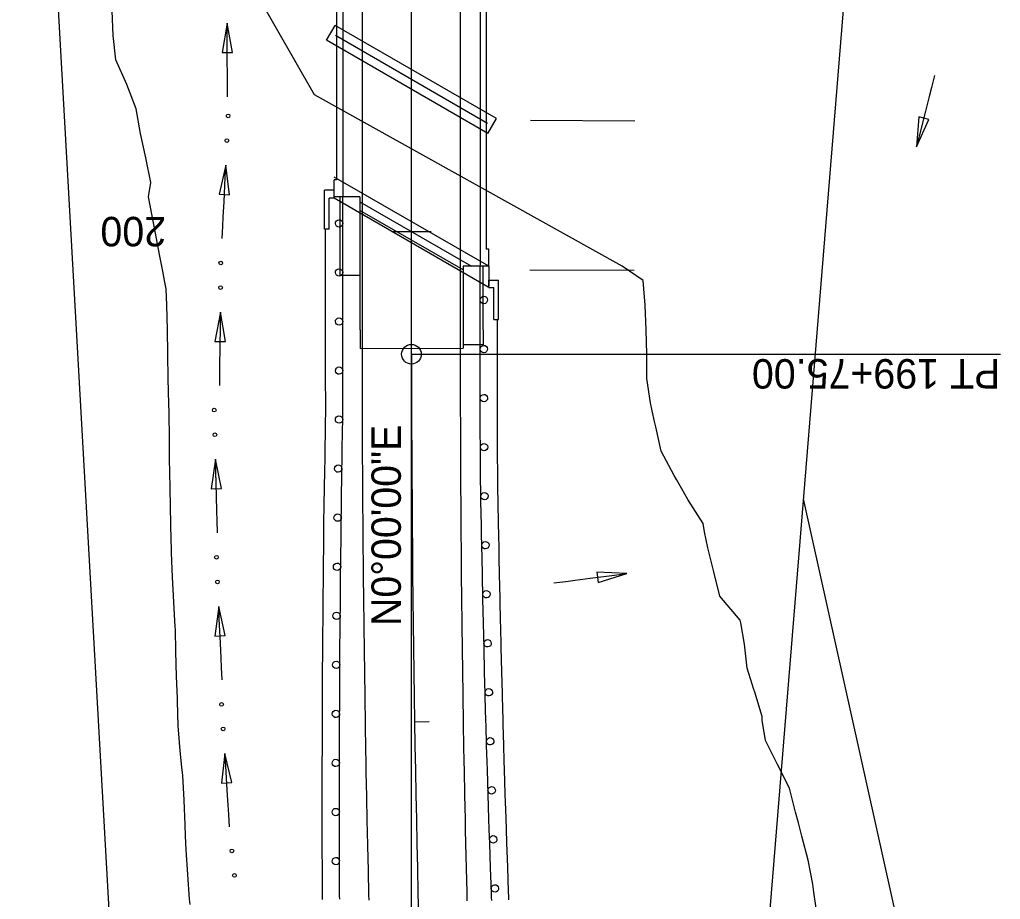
# Model space of a CAD drawing. Extents: x 1 to 1477871, y 1 to 1872901.
# Drawn here: x 1438531.3 to 1438731.2, y 1869800.2 to 1869979.6 of the extents above; entities that cross this region are included whole.
import ezdxf

# ---------------------------------------------------------------- set-up
doc = ezdxf.new("R2010")
doc.units = 0
for name, color, linetype in [('B_Centerline', 7, 'Continuous'), ('B_Concrete', 7, 'Continuous'), ('B_Concrete hidden', 7, 'Continuous'), ('R_Concrete Hidden', 7, 'Continuous'), ('R_Horz Alg', 7, 'Continuous'), ('R_Horz Alg Annot', 7, 'Continuous'), ('R_No Plot', 7, 'Continuous'), ('R_Proposed Const Limits_Cut', 7, 'Continuous'), ('R_Proposed Road_Lane', 7, 'Continuous'), ('R_Proposed Road_Shoulder', 7, 'Continuous'), ('R_ROW', 7, 'Continuous'), ('R_Steel', 7, 'Continuous'), ('R_Temp Easement', 7, 'Continuous'), ('R_Water', 7, 'Continuous')]:
    doc.layers.add(name, color=color, linetype=linetype)

msp = doc.modelspace()

# ---------------------------------------------------------------- linework, layer by layer
at = {"layer": 'B_Centerline'}
msp.add_line((1438626.69, 1869958.4), (1438595.69, 1869976.3), dxfattribs=at)
at = {"layer": 'B_Concrete'}
for p, q in [((1438597.19, 1870067.43), (1438597.19, 1869943.43)), ((1438595.94, 1870063.93), (1438595.94, 1869946.93)), ((1438625.19, 1870053.28), (1438625.19, 1869929.28)), ((1438626.44, 1870049.78), (1438626.44, 1869932.78)), ((1438595.44, 1869943.43), (1438595.44, 1869946.93)), ((1438595.94, 1869946.93), (1438595.44, 1869946.93)), ((1438593.44, 1869936.81), (1438593.44, 1869944.81)), ((1438595.44, 1869944.81), (1438593.44, 1869944.81)), ((1438595.44, 1869943.14), (1438595.44, 1869944.81)), ((1438594.44, 1869936.81), (1438594.44, 1869943.14)), ((1438595.44, 1869943.14), (1438594.44, 1869943.14)), ((1438600.69, 1869943.43), (1438595.44, 1869943.43)), ((1438596.61, 1869943.43), (1438596.61, 1869927.43)), ((1438600.69, 1869943.43), (1438600.69, 1869916.35)), ((1438600.69, 1869942.41), (1438623.44, 1869929.28)), ((1438621.69, 1869928.56), (1438600.69, 1869940.68)), ((1438594.44, 1869936.81), (1438593.44, 1869936.81)), ((1438626.94, 1869932.78), (1438626.44, 1869932.78)), ((1438626.94, 1869929.28), (1438626.94, 1869932.78)), ((1438626.94, 1869929.28), (1438621.69, 1869929.28)), ((1438621.69, 1869929.28), (1438621.69, 1869928.56)), ((1438621.69, 1869928.56), (1438621.69, 1869916.35)), ((1438626.94, 1869929.28), (1438626.94, 1869925.24)), ((1438596.61, 1869927.43), (1438600.69, 1869927.43)), ((1438626.94, 1869926.45), (1438628.94, 1869926.45)), ((1438626.94, 1869924.95), (1438626.94, 1869926.45)), ((1438628.94, 1869918.45), (1438628.94, 1869926.45)), ((1438626.94, 1869924.95), (1438627.94, 1869924.95)), ((1438627.94, 1869918.45), (1438627.94, 1869924.95)), ((1438627.94, 1869918.45), (1438628.94, 1869918.45)), ((1438600.7, 1869912.53), (1438621.7, 1869912.56)), ((1438625.78, 1869913.28), (1438621.7, 1869913.28))]:
    msp.add_line(p, q, dxfattribs=at)
msp.add_lwpolyline([(1438625.78, 1869916.35), (1438625.78, 1869916.35), (1438625.78, 1869929.28)], dxfattribs=at)
for radius, end in [(3284.54, 180.06661), (3263.55, 180.06661), (3259.46, 180.05393)]:
    msp.add_arc((1441885.24, 1869916.35), radius, 180, end, dxfattribs=at)
at = {"layer": 'B_Concrete hidden'}
for p, q in [((1438628.51, 1869959.37), (1438595.61, 1869978.37)), ((1438626.94, 1869929.28), (1438595.44, 1869947.47)), ((1438626.82, 1869925.02), (1438595.44, 1869943.14))]:
    msp.add_line(p, q, dxfattribs=at)
at = {"layer": 'R_Concrete Hidden'}
for p, q in [((1438593.86, 1869975.34), (1438595.61, 1869978.37)), ((1438626.76, 1869956.34), (1438593.86, 1869975.34)), ((1438626.76, 1869956.34), (1438628.51, 1869959.37))]:
    msp.add_line(p, q, dxfattribs=at)
at = {"layer": 'R_Horz Alg'}
msp.add_line((1438611.19, 1869911.35), (1438611.19, 1870085.35), dxfattribs=at)
msp.add_arc((1443194.86, 1869911.35), 4583.66, 180, 183.99213, dxfattribs=at)
at = {"layer": 'R_Horz Alg Annot'}
msp.add_line((1438611.19, 1869751.6), (1438611.19, 1869911.35), dxfattribs=at)
for points in [[(1438607.19, 1869936.35), (1438615.19, 1869936.35)], [(1438611.19, 1869911.35), (1438731.19, 1869911.35)], [(1438614.81, 1869836.41), (1438611.81, 1869836.36)]]:
    msp.add_lwpolyline(points, dxfattribs=at)
msp.add_circle((1438611.19, 1869911.35), 2, dxfattribs=at)
at = {"layer": 'R_No Plot'}
for p, q in [((1438635.47, 1869959.05), (1438656.69, 1869958.95)), ((1438635.32, 1869928.55), (1438656.54, 1869928.45))]:
    msp.add_line(p, q, dxfattribs=at)
at = {"layer": 'R_Proposed Const Limits_Cut'}
for points in [[(1438654.11, 1869929.27), (1438591.42, 1869964.25), (1438576.24, 1869990.87), (1438572, 1869991.35)], [(1438566.07, 1869799.15), (1438565.97, 1869800.25), (1438565.6, 1869805.29), (1438565.29, 1869810.33), (1438565.16, 1869813.16), (1438565.07, 1869815.38), (1438564.89, 1869820.43), (1438564.57, 1869825.48), (1438564.37, 1869827.18), (1438564.05, 1869830.52), (1438563.72, 1869834.74), (1438563.68, 1869835.57), (1438563.5, 1869840.62), (1438563.48, 1869841.2), (1438563.32, 1869845.67), (1438563.2, 1869850.72), (1438563.07, 1869855.22), (1438563.04, 1869855.77), (1438562.77, 1869860.82), (1438562.51, 1869865.87), (1438562.36, 1869869.25), (1438562.3, 1869870.93), (1438562.2, 1869874.28), (1438562.16, 1869875.98), (1438562.08, 1869881.03), (1438562.04, 1869883.28), (1438561.99, 1869885.26), (1438561.98, 1869886.08), (1438561.87, 1869891.14), (1438561.85, 1869896.19), (1438561.83, 1869897.32), (1438561.8, 1869899.55), (1438561.76, 1869901.25), (1438561.64, 1869906.3), (1438561.54, 1869911.35), (1438561.45, 1869916.35), (1438561.36, 1869921.35), (1438561.17, 1869924.67), (1438560.85, 1869926.35), (1438560.49, 1869928.27), (1438560.3, 1869929.28), (1438559.91, 1869931.35), (1438558.96, 1869936.35), (1438558.01, 1869941.35), (1438557.63, 1869943.42), (1438558.11, 1869946.35), (1438557.08, 1869951.35), (1438556, 1869956.35), (1438555.09, 1869961.35), (1438553.19, 1869966.35), (1438550.94, 1869971.35), (1438550.37, 1869976.35), (1438550.17, 1869981.35)], [(1438693.68, 1869798.4), (1438693.21, 1869801.65), (1438693.13, 1869802.23), (1438692.98, 1869803.29), (1438692.04, 1869808.19), (1438690.75, 1869813.07), (1438690.03, 1869815.81), (1438689.46, 1869817.96), (1438688.19, 1869822.85), (1438685.8, 1869827.73), (1438684.97, 1869829.37), (1438683.33, 1869832.6), (1438682.65, 1869836.71), (1438682.62, 1869837.52), (1438681.16, 1869842.42), (1438680.98, 1869842.98), (1438679.58, 1869847.32), (1438679.05, 1869852.24), (1438678.28, 1869856.62), (1438678.15, 1869857.15), (1438674.05, 1869862.04), (1438672.79, 1869866.96), (1438671.99, 1869870.25), (1438671.6, 1869871.88), (1438670.9, 1869875.15), (1438670.6, 1869876.81), (1438667.52, 1869881.72), (1438666.27, 1869883.92), (1438665.17, 1869885.84), (1438664.71, 1869886.64), (1438662.06, 1869891.57), (1438660.98, 1869896.52), (1438660.74, 1869897.62), (1438660.26, 1869899.8), (1438659.9, 1869901.46), (1438659.15, 1869906.41), (1438659.16, 1869911.35), (1438659.04, 1869916.35), (1438658.8, 1869921.35), (1438658.53, 1869924.67), (1438658.41, 1869926.35), (1438654.11, 1869929.27)]]:
    msp.add_lwpolyline(points, dxfattribs=at)
at = {"layer": 'R_Proposed Road_Lane'}
for points in [[(1438602.54, 1869800.04), (1438602.52, 1869801.12), (1438602.4, 1869806.13), (1438602.29, 1869811.14), (1438602.23, 1869813.95), (1438602.18, 1869816.15), (1438602.08, 1869821.16), (1438601.98, 1869826.17), (1438601.95, 1869827.86), (1438601.89, 1869831.18), (1438601.82, 1869835.37), (1438601.81, 1869836.19), (1438601.73, 1869841.2), (1438601.72, 1869841.78), (1438601.66, 1869846.21), (1438601.59, 1869851.22), (1438601.53, 1869855.69), (1438601.52, 1869856.23), (1438601.47, 1869861.25), (1438601.42, 1869866.26), (1438601.38, 1869869.6), (1438601.37, 1869871.27), (1438601.34, 1869874.59), (1438601.33, 1869876.28), (1438601.29, 1869881.29), (1438601.28, 1869883.52), (1438601.27, 1869885.48), (1438601.26, 1869886.3), (1438601.24, 1869891.31), (1438601.22, 1869896.32), (1438601.22, 1869897.44), (1438601.21, 1869899.65), (1438601.21, 1869901.33), (1438601.2, 1869906.34), (1438601.19, 1869911.35), (1438601.19, 1869916.35), (1438601.19, 1869921.35), (1438601.19, 1869924.67), (1438601.19, 1869926.35), (1438601.19, 1869928.27), (1438601.19, 1869929.28), (1438601.19, 1869931.35), (1438601.19, 1869936.35), (1438601.19, 1869941.35), (1438601.19, 1869943.42), (1438601.19, 1869946.35), (1438601.19, 1869951.35), (1438601.19, 1869956.35), (1438601.19, 1869961.35), (1438601.19, 1869966.35), (1438601.19, 1869971.35), (1438601.19, 1869976.35), (1438601.19, 1869981.35)], [(1438622.55, 1869799.93), (1438622.54, 1869800.52), (1438622.51, 1869801.6), (1438622.39, 1869806.59), (1438622.28, 1869811.58), (1438622.22, 1869814.37), (1438622.18, 1869816.57), (1438622.07, 1869821.55), (1438621.98, 1869826.54), (1438621.95, 1869828.23), (1438621.89, 1869831.53), (1438621.82, 1869835.7), (1438621.81, 1869836.52), (1438621.73, 1869841.51), (1438621.72, 1869842.08), (1438621.65, 1869846.5), (1438621.59, 1869851.49), (1438621.53, 1869855.93), (1438621.52, 1869856.47), (1438621.47, 1869861.46), (1438621.41, 1869866.45), (1438621.38, 1869869.79), (1438621.37, 1869871.44), (1438621.34, 1869874.75), (1438621.33, 1869876.43), (1438621.29, 1869881.42), (1438621.28, 1869883.64), (1438621.27, 1869885.59), (1438621.26, 1869886.41), (1438621.24, 1869891.4), (1438621.22, 1869896.39), (1438621.22, 1869897.5), (1438621.21, 1869899.7), (1438621.21, 1869901.38), (1438621.2, 1869906.36), (1438621.19, 1869911.35), (1438621.19, 1869916.35), (1438621.19, 1869921.35), (1438621.19, 1869924.67), (1438621.19, 1869926.35), (1438621.19, 1869928.27), (1438621.19, 1869929.28), (1438621.19, 1869931.35), (1438621.19, 1869936.35), (1438621.19, 1869941.35), (1438621.19, 1869943.42), (1438621.19, 1869946.35), (1438621.19, 1869951.35), (1438621.19, 1869956.35), (1438621.19, 1869961.35), (1438621.19, 1869966.35), (1438621.19, 1869971.35), (1438621.19, 1869976.35), (1438621.19, 1869981.35)]]:
    msp.add_lwpolyline(points, dxfattribs=at)
at = {"layer": 'R_Proposed Road_Shoulder'}
for points in [[(1438593.06, 1869800.21), (1438593.05, 1869800.9), (1438593.03, 1869805.92), (1438593.02, 1869810.94), (1438593.02, 1869813.75), (1438593.02, 1869815.96), (1438593.02, 1869820.98), (1438593.02, 1869826.01), (1438593.02, 1869827.7), (1438593.03, 1869831.03), (1438593.04, 1869835.23), (1438593.04, 1869836.05), (1438593.06, 1869841.07), (1438593.07, 1869841.65), (1438593.09, 1869846.09), (1438593.12, 1869851.11), (1438593.15, 1869855.59), (1438593.16, 1869856.13), (1438593.2, 1869861.15), (1438593.25, 1869866.18), (1438593.28, 1869869.53), (1438593.3, 1869871.2), (1438593.34, 1869874.53), (1438593.36, 1869876.22), (1438593.43, 1869881.24), (1438593.46, 1869883.47), (1438593.48, 1869885.43), (1438593.5, 1869886.26), (1438593.57, 1869891.28), (1438593.65, 1869896.29), (1438593.67, 1869897.41), (1438593.71, 1869899.63), (1438593.71, 1869901.31), (1438593.7, 1869906.33), (1438593.69, 1869911.35), (1438593.69, 1869916.35), (1438593.69, 1869921.35), (1438593.69, 1869924.67), (1438593.69, 1869926.35), (1438593.69, 1869928.27), (1438593.69, 1869929.28), (1438593.69, 1869931.35), (1438593.69, 1869936.35), (1438593.69, 1869936.81)], [(1438631.03, 1869800.13), (1438631.01, 1869800.73), (1438630.97, 1869801.81), (1438630.8, 1869806.78), (1438630.63, 1869811.76), (1438630.54, 1869814.55), (1438630.47, 1869816.74), (1438630.31, 1869821.72), (1438630.16, 1869826.7), (1438630.1, 1869828.37), (1438630.01, 1869831.67), (1438629.89, 1869835.83), (1438629.87, 1869836.65), (1438629.73, 1869841.63), (1438629.72, 1869842.2), (1438629.6, 1869846.61), (1438629.48, 1869851.59), (1438629.37, 1869856.03), (1438629.36, 1869856.57), (1438629.24, 1869861.55), (1438629.13, 1869866.53), (1438629.06, 1869869.86), (1438629.03, 1869871.51), (1438628.96, 1869874.81), (1438628.93, 1869876.49), (1438628.84, 1869881.47), (1438628.8, 1869883.69), (1438628.77, 1869885.63), (1438628.76, 1869886.45), (1438628.74, 1869891.43), (1438628.72, 1869896.41), (1438628.72, 1869897.52), (1438628.71, 1869899.72), (1438628.71, 1869901.39), (1438628.7, 1869906.37), (1438628.69, 1869911.35), (1438628.69, 1869916.35), (1438628.69, 1869918.45)]]:
    msp.add_lwpolyline(points, dxfattribs=at)
at = {"layer": 'R_ROW'}
for p, q in [((1438587.34, 1869127.27), (1438531.34, 1870121.98)), ((1438701.19, 1870006.35), (1438676.17, 1869699.24))]:
    msp.add_line(p, q, dxfattribs=at)
at = {"layer": 'R_Steel'}
for points in [[(1438596.56, 1869800.22), (1438596.55, 1869800.91), (1438596.53, 1869805.93), (1438596.52, 1869810.95), (1438596.52, 1869813.76), (1438596.52, 1869815.96), (1438596.52, 1869820.98), (1438596.52, 1869826), (1438596.52, 1869827.69), (1438596.53, 1869831.02), (1438596.54, 1869835.22), (1438596.54, 1869836.04), (1438596.56, 1869841.05), (1438596.57, 1869841.63), (1438596.59, 1869846.07), (1438596.62, 1869851.09), (1438596.65, 1869855.56), (1438596.66, 1869856.1), (1438596.7, 1869861.12), (1438596.75, 1869866.14), (1438596.78, 1869869.49), (1438596.84, 1869874.49), (1438596.86, 1869876.17), (1438596.93, 1869881.19), (1438596.96, 1869883.43), (1438596.98, 1869885.38), (1438597, 1869886.2), (1438597.07, 1869891.22), (1438597.15, 1869896.24), (1438597.17, 1869897.35), (1438597.21, 1869899.6), (1438597.2, 1869901.32), (1438597.2, 1869906.34), (1438597.19, 1869911.35), (1438597.19, 1869943.43)], [(1438627.53, 1869800.01), (1438627.51, 1869800.6), (1438627.47, 1869801.68), (1438627.3, 1869806.66), (1438627.13, 1869811.64), (1438627.04, 1869814.43), (1438626.97, 1869816.63), (1438626.81, 1869821.61), (1438626.66, 1869826.59), (1438626.61, 1869828.27), (1438626.51, 1869831.57), (1438626.39, 1869835.74), (1438626.37, 1869836.55), (1438626.23, 1869841.54), (1438626.22, 1869842.11), (1438626.1, 1869846.52), (1438625.98, 1869851.5), (1438625.86, 1869856.49), (1438625.74, 1869861.47), (1438625.63, 1869866.45), (1438625.56, 1869869.79), (1438625.46, 1869874.75), (1438625.43, 1869876.42), (1438625.34, 1869881.4), (1438625.3, 1869883.63), (1438625.27, 1869885.59), (1438625.26, 1869886.43), (1438625.24, 1869891.41), (1438625.22, 1869896.4), (1438625.21, 1869899.71), (1438625.21, 1869901.38), (1438625.2, 1869906.37), (1438625.19, 1869911.35), (1438625.19, 1869929.28)]]:
    msp.add_lwpolyline(points, dxfattribs=at)
for centre, major_axis in [((1438596.44, 1869938.01), (-0.512, -0.548)), ((1438596.44, 1869928.01), (-0.512, -0.548)), ((1438625.94, 1869922.4), (-0.512, -0.548)), ((1438596.44, 1869918.01), (-0.512, -0.548)), ((1438625.94, 1869912.4), (-0.512, -0.548)), ((1438596.45, 1869908.01), (-0.512, -0.548)), ((1438625.95, 1869902.4), (-0.511, -0.549)), ((1438596.43, 1869898.03), (-0.522, -0.539)), ((1438625.98, 1869892.4), (-0.51, -0.55)), ((1438596.27, 1869888.03), (-0.52, -0.54)), ((1438626.07, 1869882.41), (-0.503, -0.557)), ((1438596.14, 1869878.03), (-0.519, -0.541)), ((1438626.26, 1869872.41), (-0.501, -0.558)), ((1438596.02, 1869868.02), (-0.518, -0.542)), ((1438626.47, 1869862.42), (-0.5, -0.559)), ((1438595.93, 1869858.02), (-0.517, -0.543)), ((1438626.7, 1869852.42), (-0.498, -0.56)), ((1438595.85, 1869848.02), (-0.516, -0.544)), ((1438626.96, 1869842.43), (-0.497, -0.562)), ((1438595.8, 1869838.02), (-0.515, -0.546)), ((1438627.23, 1869832.43), (-0.496, -0.563)), ((1438595.77, 1869828.02), (-0.513, -0.547)), ((1438627.53, 1869822.44), (-0.495, -0.564)), ((1438595.77, 1869818.02), (-0.512, -0.548)), ((1438627.85, 1869812.45), (-0.494, -0.565)), ((1438595.78, 1869808.02), (-0.511, -0.549)), ((1438628.19, 1869802.45), (-0.492, -0.566))]:
    msp.add_ellipse(centre, major_axis=major_axis, ratio=0.998743, dxfattribs=at)
at = {"layer": 'R_Temp Easement'}
msp.add_line((1438731.11, 1869701.82), (1438691.05, 1869881.87), dxfattribs=at)
at = {"layer": 'R_Water'}
for p, q in [((1438573.61, 1869978.85), (1438572.59, 1869972.84)), ((1438574.71, 1869972.86), (1438573.61, 1869978.85)), ((1438572.59, 1869972.84), (1438574.71, 1869972.86)), ((1438714.55, 1869959.72), (1438714.09, 1869953.64)), ((1438714.09, 1869953.64), (1438716.6, 1869959.19)), ((1438716.6, 1869959.19), (1438714.55, 1869959.72)), ((1438573.36, 1869949.91), (1438572.01, 1869943.97)), ((1438574.12, 1869943.87), (1438573.36, 1869949.91)), ((1438572.01, 1869943.97), (1438574.12, 1869943.87)), ((1438572.26, 1869919.94), (1438571.15, 1869913.95)), ((1438573.26, 1869913.93), (1438572.26, 1869919.94)), ((1438571.15, 1869913.95), (1438573.26, 1869913.93)), ((1438571.28, 1869889.94), (1438570.37, 1869883.91)), ((1438572.49, 1869883.97), (1438571.28, 1869889.94)), ((1438570.37, 1869883.91), (1438572.49, 1869883.97)), ((1438655.06, 1869866.61), (1438648.97, 1869866.91)), ((1438648.97, 1869866.91), (1438649.24, 1869864.81)), ((1438649.24, 1869864.81), (1438655.06, 1869866.61)), ((1438571.92, 1869859.94), (1438571.13, 1869853.9)), ((1438573.25, 1869854), (1438571.92, 1869859.94)), ((1438571.13, 1869853.9), (1438573.25, 1869854)), ((1438573.17, 1869829.97), (1438572.5, 1869823.91)), ((1438574.61, 1869824.05), (1438573.17, 1869829.97)), ((1438572.5, 1869823.91), (1438574.61, 1869824.05))]:
    msp.add_line(p, q, dxfattribs=at)
for points in [[(1438573.73, 1869963.85), (1438573.7, 1869966.37), (1438573.69, 1869968.25), (1438573.66, 1869971.35), (1438573.63, 1869976.34), (1438573.61, 1869978.85)], [(1438717.8, 1869968.18), (1438717.18, 1869965.73), (1438716.71, 1869963.91), (1438715.95, 1869960.91), (1438714.71, 1869956.08), (1438714.09, 1869953.64)], [(1438572.62, 1869934.93), (1438572.75, 1869937.45), (1438572.84, 1869939.33), (1438572.99, 1869942.42), (1438573.23, 1869947.4), (1438573.36, 1869949.91)], [(1438572.13, 1869904.94), (1438572.15, 1869907.46), (1438572.17, 1869909.34), (1438572.19, 1869912.44), (1438572.24, 1869917.42), (1438572.26, 1869919.94)], [(1438571.66, 1869874.94), (1438571.59, 1869877.46), (1438571.55, 1869879.34), (1438571.47, 1869882.44), (1438571.34, 1869887.42), (1438571.28, 1869889.94)], [(1438640.17, 1869864.72), (1438642.67, 1869865.04), (1438644.54, 1869865.28), (1438647.62, 1869865.67), (1438652.56, 1869866.29), (1438655.06, 1869866.61)], [(1438572.6, 1869844.96), (1438572.48, 1869847.47), (1438572.4, 1869849.36), (1438572.26, 1869852.45), (1438572.03, 1869857.43), (1438571.92, 1869859.94)], [(1438574.14, 1869815), (1438573.98, 1869817.51), (1438573.85, 1869819.39), (1438573.65, 1869822.48), (1438573.33, 1869827.46), (1438573.17, 1869829.97)]]:
    msp.add_lwpolyline(points, dxfattribs=at)
for centre in [(1438573.82, 1869959.92), (1438573.57, 1869954.91), (1438572.33, 1869929.95), (1438572.28, 1869924.94), (1438571, 1869899.95), (1438571.12, 1869894.94), (1438571.44, 1869869.95), (1438571.66, 1869864.94), (1438572.49, 1869839.96), (1438572.81, 1869834.96), (1438574.6, 1869810.09), (1438575.1, 1869805.1)]:
    msp.add_circle(centre, 0.375, dxfattribs=at)

# ---------------------------------------------------------------- texts
at = {"layer": 'R_Horz Alg Annot'}
for s, rotation, p in [('200', 180, (1438561.19, 1869939.35)), ('PT 199+75.00', 180, (1438731.19, 1869910.35)), ('N0%%d00\'00"E', 90, (1438609.03, 1869855.93))]:
    msp.add_text(s, height=6, rotation=rotation, dxfattribs=at).set_placement(p)

doc.saveas('drawing.dxf')
